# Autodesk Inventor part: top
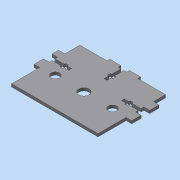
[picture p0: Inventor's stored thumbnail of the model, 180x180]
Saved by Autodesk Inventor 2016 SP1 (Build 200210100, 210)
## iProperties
Created: 2016-06
Part Number: top
Material: Generic
Document SubType Name: Modeling
Designer: Mohamed A.
Density: 1 g/cm^3
Appearance: Default
Author: Mohamed A.
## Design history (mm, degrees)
sketch "Sketch1"
  geometry: L1 (46, 2.505)-(52, 2.505) reference; L2 (52, -7.495)-(52, 2.505) reference; L3 (46, -7.495)-(52, -7.495) reference; L4 (46, -7.495)-(46, -37.5) reference; L5 (46, -37.5)-(-46, -37.5) reference; L6 (-46, -37.5)-(-46, -7.495) reference; L7 (-46, -7.495)-(-52, -7.495) reference; L8 (-52, 2.505)-(-52, -7.495) reference; L9 (-46, 2.505)-(-52, 2.505) reference; L10 (-46, 2.505)-(-46, 5.455) reference; L11 (-46, 5.455)-(-36, 5.455) reference; L12 (-36, 5.455)-(-36, 4.005) reference; L13 (-36, 4.005)-(-33, 4.005) reference; L14 (-33, 4.005)-(-33, 5.455) reference; L15 (-33, 5.455)-(-28, 5.455) reference; L16 (-28, 5.455)-(-28, 8.555) reference; L17 (-28, 8.555)-(-33, 8.555) reference; L18 (-33, 8.555)-(-33, 10.005) reference; L19 (-33, 10.005)-(-36, 10.005) reference; L20 (-36, 10.005)-(-36, 8.555) reference; L21 (-36, 8.555)-(-46, 8.555) reference; L22 (-46, 8.555)-(-46, 11.505) reference; L23 (-46, 11.505)-(-52, 11.505) reference; L24 (-52, 18.555)-(-52, 11.505) reference; L25 (-52, 18.555)-(-45.295, 18.555) reference; L26 (-45.295, 18.555)-(-45.295, 34.5) reference; L27 (-45.295, 34.5)-(-16.333, 34.5) reference; L28 (-16.333, 34.5)-(-16.333, 37.5) reference; L29 (-16.333, 37.5)-(-4.5, 37.5) reference; L30 (-4.5, 37.5)-(-4.5, 34.5) reference; L31 (-4.5, 34.5)-(-1.55, 34.5) reference; L32 (-1.55, 34.5)-(-1.55, 24.5) reference; L33 (-1.55, 24.5)-(-3, 24.5) reference; L34 (-3, 24.5)-(-3, 21.5) reference; L35 (-3, 21.5)-(-1.55, 21.5) reference; L36 (-1.55, 21.5)-(-1.55, 16.5) reference; L37 (-1.55, 16.5)-(1.55, 16.5) reference; L38 (1.55, 16.5)-(1.55, 21.5) reference; L39 (1.55, 21.5)-(3, 21.5) reference; L40 (3, 21.5)-(3, 24.5) reference; L41 (3, 24.5)-(1.55, 24.5) reference; L42 (1.55, 24.5)-(1.55, 34.5) reference; L43 (1.55, 34.5)-(4.5, 34.5) reference; L44 (4.5, 34.5)-(4.5, 37.5) reference; L45 (4.5, 37.5)-(16.333, 37.5) reference; L46 (16.333, 37.5)-(16.333, 34.5) reference; L47 (16.333, 34.5)-(46, 34.5) reference; L48 (46, 34.5)-(46, 21.505) reference; L49 (46, 21.505)-(52, 21.505) reference; L50 (52, 11.505)-(52, 21.505) reference; L51 (46, 11.505)-(52, 11.505) reference; L52 (46, 11.505)-(46, 8.555) reference; L53 (46, 8.555)-(36, 8.555) reference; L54 (36, 8.555)-(36, 10.005) reference; L55 (36, 10.005)-(33, 10.005) reference; L56 (33, 10.005)-(33, 8.555) reference; L57 (33, 8.555)-(28, 8.555) reference; L58 (28, 8.555)-(28, 5.455) reference; L59 (28, 5.455)-(33, 5.455) reference; L60 (33, 5.455)-(33, 4.005) reference; L61 (33, 4.005)-(36, 4.005) reference; L62 (36, 4.005)-(36, 5.455) reference; L63 (36, 5.455)-(46, 5.455) reference; L64 (46, 5.455)-(46, 2.505) reference; C1 r 4.5 at (30.5, -6.5) reference; C2 r 1.4 at (15.5, -22) reference; C3 r 1.4 at (-15.5, 9) reference; C4 r 1.4 at (15.5, 9) reference; C5 r 1.4 at (-15.5, -22) reference; C6 r 4.5 at (-30.5, -6.5) reference; C7 r 12.5 at (0, -6.5) reference
extrude "Extrusion1" new body sketch "Sketch1" distance "d2" = 3; taper "d3" = 0 deg
sketch "Sketch2"
  geometry: C1 r 4.5 at (30.5, -6.5) reference; C2 r 3.5 at (0, -6.5) reference; C3 r 4.5 at (-30.5, -6.5) reference; C4 r 5.5 at (0, -6.5); 1 further point
  constraints: 1 centre point
  dimensions: "d4" = 2 radial gap between concentric circles of C2 C4
extrude "Extrusion2" cut sketch "Sketch2" distance "d5" = 3; taper "d6" = 0 deg
sketch "Sketch3"
  geometry: 1 further point
body "Solid1"
node "Reference1"
node "Reference2"
node "Reference3"
node "Reference4"
